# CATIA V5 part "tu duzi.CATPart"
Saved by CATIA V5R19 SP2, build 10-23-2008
Part number: tu duzi
Bounding box of the stored display mesh (mm): x -139.503 to 1318.778, y -749.046 to 748.093, z -3.905 to 999.658
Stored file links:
  C:\BEHROOZ\catia learning\tarh haye mashin\hb\tu duzi.CATPart
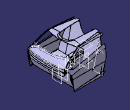
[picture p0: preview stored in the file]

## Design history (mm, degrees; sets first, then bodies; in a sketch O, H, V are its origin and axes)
Body1 (main body)
  DatumSurface1
  ThickSurface1: Surface DatumSurface1, TopOffset 6, BotOffset 0
  DatumSurface2
  ThickSurface2: Surface DatumSurface2, TopOffset 6, BotOffset 0
  DatumSurface3
  ThickSurface3: Surface DatumSurface3, TopOffset 6, BotOffset 0
  DatumSurface4
  ThickSurface4: Surface DatumSurface4, TopOffset 6, BotOffset 0
  DatumSurface5
  ThickSurface5: Surface DatumSurface5, TopOffset 6, BotOffset 0
  DatumSurface6
  ThickSurface6: Surface DatumSurface6, TopOffset 6, BotOffset 0
  DatumSurface7
  DatumSurface8
  ThickSurface7: Surface DatumSurface8, TopOffset 6, BotOffset 0
  DatumSurface9
  ThickSurface8: Surface DatumSurface9, TopOffset 6, BotOffset 0
  DatumSurface10
  ThickSurface9: Surface DatumSurface10, TopOffset 6, BotOffset 0
  DatumSurface11
  ThickSurface10: Surface DatumSurface11, TopOffset 6, BotOffset 0
  DatumSurface12
  ThickSurface11: Surface DatumSurface12, TopOffset 6, BotOffset 0
  DatumSurface13
  ThickSurface12: Surface DatumSurface13, TopOffset 6, BotOffset 0
  DatumSurface14
  ThickSurface13: Surface DatumSurface14, TopOffset 6, BotOffset 0
  DatumSurface15
  ThickSurface14: Surface DatumSurface15, TopOffset 6, BotOffset 0
  DatumSurface16
  ThickSurface15: Surface DatumSurface16, TopOffset 6, BotOffset 0
  DatumSurface17
  ThickSurface16: Surface DatumSurface17, TopOffset 6, BotOffset 0
  DatumSurface18
  ThickSurface17: Surface DatumSurface18, TopOffset 6, BotOffset 0
  DatumSurface19 to DatumSurface21
  ThickSurface18: Surface DatumSurface21, TopOffset 6, BotOffset -1
  DatumSurface22
  ThickSurface19: Surface DatumSurface22, TopOffset 6, BotOffset -1
  DatumSurface23
  ThickSurface20: Surface DatumSurface23, TopOffset 5, BotOffset -2
  DatumSurface24
  ThickSurface21: Surface DatumSurface24, TopOffset 5, BotOffset -2
  DatumSurface25
  ThickSurface22: Surface DatumSurface25, TopOffset 6, BotOffset -1
  DatumSurface26
  ThickSurface23: Surface DatumSurface26, TopOffset 13, BotOffset -2
  DatumSurface27
  ThickSurface24: Surface DatumSurface27, TopOffset 13, BotOffset -2
  DatumSurface28
  ThickSurface25: Surface DatumSurface28, TopOffset 13, BotOffset -2
  DatumSurface29
  ThickSurface26: Surface DatumSurface29, TopOffset 13, BotOffset -2
  DatumSurface30
  Sketch1 on zx-plane, origin (0, 0, 0), H (-1, 0, 0), V (0, 0, 1)
    arc A1 centre (-3834.746, 1334.3844) radius 3989.4624 from (142.7973, 1026.2291) to (-75.0584, 0.0082) cw
    arc A2 centre (-2062.7364, 65.3843) radius 1022.0278 from (-1272.4788, 713.4843) to (-1135.4173, 495.0587) cw
    line L1 (-1030.2634, -71.027) -> (-175.6467, -71.027)
    arc A3 centre (-175.6467, 35.7087) radius 106.7357 from (-75.0584, 0.0082) to (-175.6467, -71.027) cw
    line L2 (142.7973, 1026.2291) -> (1246.4568, 1192.5653)
    line L3 (1246.4568, 1192.5653) -> (1928.7231, 515.2608)
    line L4 (1928.7231, 515.2608) -> (858.0134, -421.0131)
    line L5 (858.0134, -421.0131) -> (-1407.9072, -550.4977)
    line L6 (-1407.9072, -550.4977) -> (-2393.9563, 86.9653)
    line L7 (-2393.9563, 86.9653) -> (-2120.0717, 949.2289)
    line L8 (-2120.0717, 949.2289) -> (-1272.4788, 713.4843)
    arc A4 centre (4413.6099, 1233.0151) radius 5597.882 from (-1135.4173, 495.0587) to (-1030.2634, -71.027) ccw
  Pocket1: profile Sketch1, direction (0, -1, 0), length 2693, mirrored extent
  DatumCurve1
  Point1: type OnCurve, Support DatumCurve1, Ratio 0.5
  Curve1: Elements (vertex [face of ThickSurface22 | face of ThickSurface22 | face of Pocket1 from Sketch1.A2]; Point1; vertex [face of ThickSurface19 | face of ThickSurface19 | face of Pocket1 from Sketch1.A2])
  Point2: (-243, -5, 9), relative to vertex of Curve1
  Point3: type OnCurve, Support Curve1, Ratio 0.13
  Point4: (-367, 0, 64), relative to Point3
  Point5: type OnCurve, Support Curve1, Ratio 0.37
  Point6: (-344, 0, 51), relative to Point5
  Point7: (-309, 0, 41), relative to Point1
  Point8: type OnCurve, Support Curve1, Ratio 0.77
  Point9: (-274, 0, 30), relative to Point8
  Symmetry1: ToTransfor Point2, Reference zx-plane
  Curve2: Elements (Symmetry1; Point9; Point7; Point6; Point4; Point2)
  Curve3: Elements (vertex of Curve1; Point2)
  Curve4: Elements (vertex of Curve1; Symmetry1)
  Corner1: Element1 Curve4, Element2 Curve2, Radius 107, Direction (0, 0, 1)
  Fill1: Boundary (Curve1; Corner1; Curve3)
  ThickSurface27: Surface Fill1, TopOffset 13, BotOffset -2
  Fillet1: radius 5, on face of ThickSurface27
  Plane1: type Offset, RefPlane xy-plane, Offset 449
  Sketch2 on Plane1, origin (0, 0, 449), H (1, 0, 0), V (0, 1, 0)
    line L1 (1222.6008, 607.4376) -> (1236.6342, 604.8067)
    arc A1 centre (1277.6367, -160.9425) radius 446.4787 from (1228.4764, -604.7066) to (1153.9503, -589.9471) cw
    arc A2 centre (-667.988, -264.4361) radius 1745.864 from (1066.9231, -459.6915) to (985.4739, 296.0145) ccw
    arc A3 centre (1220.2137, 375.581) radius 247.8581 from (985.4739, 296.0145) to (1057.5641, 562.607) cw
    arc A4 centre (1187.589, -473.2718) radius 121.4277 from (1153.9503, -589.9471) to (1066.9231, -459.6915) cw
    arc A5 centre (-4227.7674, 36.878) radius 5493.8354 from (1236.6342, 604.8067) to (1228.4764, -604.7066) cw
    arc A6 centre (1186.4195, 414.44) radius 196.3598 from (1057.5641, 562.607) to (1222.6008, 607.4376) cw
  Pad1: profile Sketch2, direction (0, 0, 1), up to face of ThickSurface27, opposite side length 18
  DatumCurve2
  RectPattern1: of ThickSurface27, direction 1 instances 2, spacing 98, along edge of DatumCurve2 reversed
  Fillet2: radius 5, on face of RectPattern1
  Plane2: type Offset, RefPlane yz-plane, Offset 694
  DatumSurface31
  Fillet3: radius 100, on edge [start face of Pad1 | face of Pad1 from Sketch2.A2]
  Join1: Elements (face of Pad1 from Sketch2.A3; face of Pad1 from Sketch2.A2)
  Plane3: type Offset, RefPlane Plane2, Offset 188
  Sketch3 on Plane3, origin (882, 0, 0), H (0, 1, 0), V (0, 0, 1)
    arc A1 centre (508.6645, 605.7318) radius 48.7497 from (541.1131, 569.3502) to (463.6433, 587.0334) ccw
    arc A2 centre (392.1984, 622.2132) radius 47.1664 from (427.7856, 591.258) to (354.8225, 593.4432) ccw
    circle A3 centre (306.2773, 645.6449) radius 20.4601
    circle A4 centre (328.066, 612.2053) radius 14.5415
    circle A5 centre (289.3627, 608.9891) radius 14.5415
    circle A6 centre (250.6593, 605.7729) radius 14.5415
    circle A7 centre (211.5999, 602.0845) radius 14.5415
    circle A8 centre (228.3164, 636.5264) radius 20.4601
    circle A9 centre (453.651, 648.3524) radius 14.4124
    point P14 (441.0167, 641.4177)
    point P15 (441.0167, 641.4177)
    circle A10 centre (450.4173, 620.326) radius 5.5628
    circle A11 centre (446.9694, 603.4744) radius 5.5628
    unspec C1
    unspec C2
    coincidence: P14 P15
  Translate1: ToTransfor Join1, Direction (1, 0, 0), Length 10
  Pocket2: profile Sketch3, direction (-1, 0, 0), up to Join1, opposite side up to Translate1
  Sketch4 on Plane3, origin (882, 0, 0), H (0, 1, 0), V (0, 0, 1)
    line L1 (-422.2542, 649.9754) -> (-243.5843, 649.9754)
    line L2 (-233.5843, 639.9754) -> (-233.5843, 588.5597)
    line L3 (-243.5843, 578.5597) -> (-422.2542, 578.5597)
    line L4 (-432.2542, 588.5597) -> (-432.2542, 639.9754)
    arc A1 centre (-422.2542, 639.9754) radius 10 from (-422.2542, 649.9754) to (-432.2542, 639.9754) ccw
    arc A2 centre (-243.5843, 639.9754) radius 10 from (-243.5843, 649.9754) to (-233.5843, 639.9754) cw
    arc A3 centre (-243.5843, 588.5597) radius 10 from (-233.5843, 588.5597) to (-243.5843, 578.5597) cw
    arc A4 centre (-422.2542, 588.5597) radius 10 from (-422.2542, 578.5597) to (-432.2542, 588.5597) cw
    circle A5 centre (-190.5814, 610.2491) radius 22.9588
    circle A6 centre (-190.5814, 610.2491) radius 16.1757
    arc A7 centre (-165.5799, 609.519) radius 17.9448 from (-178.9489, 621.4891) to (-179.6246, 598.3494) ccw
    arc A8 centre (-169.5141, 610.7067) radius 24.3411 from (-188.2423, 626.2547) to (-187.5495, 594.3601) ccw
    arc A9 centre (-184.614, 610.2457) radius 19.0479 from (-196.0659, 625.4666) to (-196.0833, 595.0378) ccw
    circle A10 centre (-32.537, 612.8316) radius 22.9588
    circle A11 centre (-32.537, 612.8316) radius 16.1757
    arc A12 centre (-7.5355, 612.1016) radius 17.9448 from (-20.9045, 624.0717) to (-21.5802, 600.932) ccw
    arc A13 centre (-11.4696, 613.2893) radius 24.3411 from (-30.1979, 628.8373) to (-29.505, 596.9426) ccw
    arc A14 centre (-26.5695, 612.8282) radius 19.0479 from (-38.0215, 628.0492) to (-38.0388, 597.6204) ccw
    circle A15 centre (32.6459, 612.8316) radius 22.9588
    circle A16 centre (32.6459, 612.8316) radius 16.1757
    arc A17 centre (7.6445, 612.1016) radius 17.9448 from (21.0135, 624.0717) to (21.6892, 600.932) cw
    arc A18 centre (11.5786, 613.2893) radius 24.3411 from (30.3068, 628.8373) to (29.614, 596.9426) cw
    arc A19 centre (26.6785, 612.8282) radius 19.0479 from (38.1305, 628.0492) to (38.1478, 597.6204) cw
    circle A20 centre (121.7133, 614.7218) radius 22.9588
    circle A21 centre (121.7133, 614.7218) radius 16.1757
    arc A22 centre (96.7118, 613.9917) radius 17.9448 from (110.0809, 625.9618) to (110.7565, 602.8221) cw
    arc A23 centre (100.646, 615.1794) radius 24.3411 from (119.3742, 630.7275) to (118.6814, 598.8328) cw
    arc A24 centre (115.7459, 614.7184) radius 19.0479 from (127.1979, 629.9393) to (127.2152, 599.5105) cw
  Pocket3: profile Sketch4, direction (-1, 0, 0), up to Join1, opposite side up to Translate1, thin wall 1
  ThickSurface28: Surface face of Pad1 from Sketch2.A2, TopOffset 3, BotOffset 0
  ThickSurface29: Surface face of Pad1 from Sketch2.A2, TopOffset 3, BotOffset 0
  ThickSurface30: Surface face of Pad1 from Sketch2.A2, TopOffset 3, BotOffset 0
  ThickSurface31: Surface face of Pad1 from Sketch2.A2, TopOffset 3, BotOffset 0
  Fillet4: radius 3, on edge [face of ThickSurface31 | face of ThickSurface31]; edge [face of ThickSurface30 | face of ThickSurface30]; edge [face of ThickSurface29 | face of ThickSurface29]; edge [face of ThickSurface28 | face of ThickSurface28]
  ThickSurface32: Surface face of Pad1 from Sketch2.A2, TopOffset 3, BotOffset 0
  Fillet5: radius 3, on face of ThickSurface32
  Pocket4: profile Sketch27, direction (-1, 0, 0), up to Join1, opposite side up to Translate1, offset 2
Body2
  DatumSurface32
  DatumSurface33
  Sketch5 on zx-plane, origin (0, 0, 0), H (-1, 0, 0), V (0, 0, 1)
    arc A1 centre (-1365.5691, 2023.2833) radius 1494.6313 from (-1057.7335, 560.6966) to (-1038.1843, 564.948) ccw
    line L1 (-743.7696, 307.1377) -> (-8.4597, 307.1377)
    line L2 (-8.4597, 307.1377) -> (12.6041, 35.1694)
    line L3 (12.6041, 35.1694) -> (-972.2409, 20.8529)
    arc A2 centre (-192.6492, 564.2855) radius 950.3063 from (-972.2409, 20.8529) to (-1142.7669, 545.3517) cw
    line L4 (-1142.7669, 545.3517) -> (-1057.7335, 560.6966)
    arc A3 centre (-743.7696, 434.0399) radius 126.9022 from (-805.8167, 323.3406) to (-743.7696, 307.1377) ccw
    arc A4 centre (-523.0393, 827.8481) radius 578.3518 from (-1038.1843, 564.948) to (-805.8167, 323.3406) ccw
  Pad2: profile Sketch5, direction (0, 1, 0), length 97, mirrored extent
  Chamfer1: length 63, angle 15, on edge [face of Pad2 from Sketch5.A4 | end face of Pad2]; edge [start face of Pad2 | face of Pad2 from Sketch5.A4]
  Fillet6: radius 10, on edge [face of Pad2 from Sketch5.L1 | face of Chamfer1]; edge [face of Chamfer1 | end face of Pad2]; edge [face of Chamfer1 | face of Pad2 from Sketch5.L1]; edge [start face of Pad2 | face of Chamfer1]
  Sketch6 on end face of Pad2, origin (0, 97, 0), H (-1, 0, 0), V (0, 0, 1)
    projected line E1 (-972.2409, 20.8529) -> (12.6041, 35.1694) from edge [face of Pad2 from Sketch5.L3 | end face of Pad2]
    projected arc E2 centre (-192.6492, 564.2855) radius 950.3063 from (-1142.7669, 545.3517) to (-972.2409, 20.8529) ccw from edge [face of Pad2 from Sketch5.A2 | end face of Pad2]
  Pad3: profile Sketch6, direction (0, 1, 0), length 589, opposite side length 787, thin wall 5
  Sketch7 on end face of Pad3, origin (0, 686, 0), H (-1, 0, 0), V (0, 0, 1)
    arc A1 centre (-192.6496, 564.2854) radius 950.306 from (-1140.061, 490.1699) to (-972.2409, 20.8529) ccw
    arc A2 centre (-192.6495, 564.2854) radius 945.306 from (-1135.4097, 494.9549) to (-969.6534, 25.8911) ccw
    line L1 (-969.6534, 25.8911) -> (12.5314, 40.1688)
    line L2 (12.5314, 40.1688) -> (12.6041, 35.1694)
    line L3 (12.6041, 35.1694) -> (-972.2409, 20.8529)
    line L4 (-1140.061, 490.1699) -> (-1135.4097, 494.9549)
  Pad4: profile Sketch7, direction (0, 1, 0), length 33
  Plane4: stored without definition
  Mirror1: of Pad4, about zx-plane
  Sketch8 on Plane4, origin (0, 334, 0), H (-1, 0, 0), V (0, 0, 1)
    line L1 (-1037.4943, 536.1759) -> (-864.9229, 611.7315)
    line L2 (-864.9229, 611.7315) -> (-824.0238, 536.1759)
    arc A1 centre (-1084.6874, 728.0864) radius 323.6899 from (-824.0238, 536.1759) to (-1108.6157, 405.2822) cw
    line L3 (-1108.6157, 405.2822) -> (-1037.4943, 536.1759)
  Pad5: profile Sketch8, direction (0, 1, 0), length -30, opposite side length -119
  Fillet7: radius 39, on edge [end face of Pad5 | face of Pad5 from Sketch8.A1]; edge [face of Pad5 from Sketch8.A1 | start face of Pad5]
  Fillet8: radius 26, on edge [face of Pad5 from Sketch8.L1 | start face of Pad5]; edge [end face of Pad5 | face of Pad5 from Sketch8.L1]
  Fillet9: radius 26, on face of Pad5 from Sketch8.L2
  Pocket5: profile Sketch19, direction (0, 0, -1), length 62
  Pocket6: profile Sketch24, direction (-1, 0, 0), length 42, opposite side length 403, thin wall 1
  Sketch9 on Plane2, origin (694, 0, 0), H (0, 1, 0), V (0, 0, 1)
    line L1 (58.921, 392.5908) -> (-58.8327, 392.5908)
    line L2 (-63.8327, 387.5908) -> (-63.8327, 343.9802)
    line L3 (-58.8327, 338.9802) -> (58.921, 338.9802)
    line L4 (63.921, 343.9802) -> (63.921, 387.5908)
    line L5 (33.921, 332.2071) -> (17.7613, 332.2071)
    line L6 (17.7613, 332.2071) -> (17.7613, 326.1764)
    line L7 (17.7613, 326.1764) -> (33.921, 326.1764)
    line L8 (33.921, 326.1764) -> (33.921, 332.2071)
    line L9 (16.0193, 332.2071) -> (-0.1405, 332.2071)
    line L10 (-0.1405, 332.2071) -> (-0.1405, 326.1764)
    line L11 (-0.1405, 326.1764) -> (16.0193, 326.1764)
    line L12 (16.0193, 326.1764) -> (16.0193, 332.2071)
    line L13 (-1.8825, 332.2071) -> (-18.0422, 332.2071)
    line L14 (-18.0422, 332.2071) -> (-18.0422, 326.1764)
    line L15 (-18.0422, 326.1764) -> (-1.8825, 326.1764)
    line L16 (-1.8825, 326.1764) -> (-1.8825, 332.2071)
    line L17 (-19.7842, 332.2071) -> (-35.944, 332.2071)
    line L18 (-35.944, 332.2071) -> (-35.944, 326.1764)
    line L19 (-35.944, 326.1764) -> (-19.7842, 326.1764)
    line L20 (-19.7842, 326.1764) -> (-19.7842, 332.2071)
    arc A1 centre (58.921, 343.9802) radius 5 from (58.921, 338.9802) to (63.921, 343.9802) ccw
    arc A2 centre (-58.8327, 387.5908) radius 5 from (-58.8327, 392.5908) to (-63.8327, 387.5908) ccw
    arc A3 centre (58.921, 387.5908) radius 5 from (58.921, 392.5908) to (63.921, 387.5908) cw
    arc A4 centre (-58.8327, 343.9802) radius 5 from (-63.8327, 343.9802) to (-58.8327, 338.9802) ccw
  Pocket7: profile Sketch9, direction (-1, 0, 0), length 42, opposite side length 259, thin wall 1
  Sketch10 on end face of Pad10, origin (0, 72, 0), H (-1, 0, 0), V (0, 0, 1)
    projected arc E1 centre (-702.5644, 421.2254) radius 220.3066 from (-525.3201, 290.3841) to (-502.088, 329.8789) ccw from edge [face of Fillet21 | end face of Pad10]
    projected arc E2 centre (-472.9683, 316.6106) radius 32 from (-475.2151, 348.5317) to (-502.088, 329.8789) ccw from edge [face of Fillet21 | end face of Pad10]
    projected arc E3 centre (-119.135, -4710.4762) radius 5071.5238 from (-60.1018, 360.704) to (-475.2151, 348.5317) ccw from edge [face of Fillet21 | end face of Pad10]
  Sketch11 on face of Pad5 from Sketch8.L2, origin (412.8217, 0, -223.465), H (0, -1, 0), V (0.476, 0, 0.8794)
    line L1 (-301.2089, 888.6024) -> (-472.1108, 888.6024)
    line L2 (-472.1108, 888.6024) -> (-472.1108, 926.6243)
    line L3 (-472.1108, 926.6243) -> (-301.2089, 926.6243)
    line L4 (-301.2089, 926.6243) -> (-301.2089, 888.6024)
  Pocket8: profile Sketch11, direction (0.8794, 0, -0.476), length 32, opposite side length -44
  Sketch12 on face of Pad5 from Sketch8.L2, origin (412.8217, 0, -223.465), H (0, -1, 0), V (0.476, 0, 0.8794)
    line L1 (-429.5392, 900.6907) -> (-541.6347, 912.8104)
    line L2 (-541.6347, 912.8104) -> (-540.6042, 922.3412)
    line L3 (-540.6042, 922.3412) -> (-428.5087, 910.2216)
    line L4 (-428.5087, 910.2216) -> (-429.5392, 900.6907)
    line L5 (-335.0437, 904.0642) -> (-229.239, 910.2216)
    line L6 (-229.239, 910.2216) -> (-229.8032, 919.9166)
    line L7 (-229.8032, 919.9166) -> (-335.6079, 913.7592)
    line L8 (-335.6079, 913.7592) -> (-335.0437, 904.0642)
  Pad6: profile Sketch12, direction (-0.8794, 0, 0.476), length -32, opposite side length 42
  Sketch13 on end face of Pad6, origin (440.9633, 0, -238.6983), H (0, -1, 0), V (0.476, 0, 0.8794)
    line L1 (-517.7755, 921.4397) -> (-555.3917, 930.3889)
    line L2 (-555.3917, 930.3889) -> (-558.0523, 911.042)
    line L3 (-558.0523, 911.042) -> (-519.6631, 908.7501)
    line L4 (-519.6631, 908.7501) -> (-517.7755, 921.4397)
    axis line L5 (-380.4079, 896.7881) -> (-380.4079, 939.3172)
    line L6 (-241.0901, 920.7533) -> (-206.5129, 928.7124)
    line L7 (-206.5129, 928.7124) -> (-204.5656, 909.1401)
    line L8 (-204.5656, 909.1401) -> (-239.9875, 907.9052)
    line L9 (-239.9875, 907.9052) -> (-241.0901, 920.7533)
  Pad7: profile Sketch13, direction (-0.8794, 0, 0.476), length -14, opposite side length -4
  Fillet10: radius 4.7, on edge [face of Pad6 from Sketch12.L3 | end face of Pad6]; edge [face of Pad6 from Sketch12.L1 | end face of Pad6]; edge [start face of Pad6 | face of Pad6 from Sketch12.L3]; edge [start face of Pad6 | face of Pad6 from Sketch12.L1]; edge [face of Pad6 from Sketch12.L5 | end face of Pad6]; edge [face of Pad6 from Sketch12.L7 | end face of Pad6]; edge [start face of Pad6 | face of Pad6 from Sketch12.L7]; edge [start face of Pad6 | face of Pad6 from Sketch12.L5]
  Fillet11: radius 5.7, on edge [face of Pad7 from Sketch13.L6 | start face of Pad7]; edge [end face of Pad7 | face of Pad7 from Sketch13.L6]; edge [face of Pad7 from Sketch13.L8 | start face of Pad7]; edge [end face of Pad7 | face of Pad7 from Sketch13.L8]; edge [face of Pad7 from Sketch13.L1 | start face of Pad7]; edge [end face of Pad7 | face of Pad7 from Sketch13.L1]; edge [face of Pad7 from Sketch13.L3 | start face of Pad7]; edge [end face of Pad7 | face of Pad7 from Sketch13.L3]
  Fillet12: radius 1.7, on face of Pad7 from Sketch13.L2; face of Pad7 from Sketch13.L7; edge [face of Pad7 from Sketch13.L6 | face of Pad7 from Sketch13.L9]; edge [face of Pad7 from Sketch13.L4 | face of Pad7 from Sketch13.L1]
Body3
  Point10: type OnPlane, Support face of Pad5 from Sketch8.L2, H -379.62, V 902.1, Direction (0, -1, 0)
  Line1: type PtDir, RefPoint Point10, Direction face of Pad5 from Sketch8.L2, Start -65, End 20
  Plane5: stored without definition
  Plane6: type OffsetPt, RefPlane Plane5, RefPoint Point10
  Sketch14 on Plane6, origin (0, 379.62, 0), H (-1, 0, 0), V (0, 0, 1)
    line L1 (-853.538, 590.6995) -> (-839.8717, 612.8699)
    line L2 (-839.8717, 612.8699) -> (-836.287, 610.6602)
    line L3 (-836.287, 610.6602) -> (-842.4641, 621.3408)
    line L4 (-842.5175, 570.3474) -> (-853.538, 590.6995)
    line L5 (-842.4641, 621.3408) -> (-831.283, 635.0107)
    arc A1 centre (-994.6494, 680.8433) radius 169.6738 from (-831.283, 635.0107) to (-825.716, 696.6769) ccw
    arc A2 centre (-429.2762, 749.9084) radius 386.03 from (-812.8779, 706.678) to (-785.8484, 602.0049) ccw
    line L6 (-785.8484, 602.0049) -> (-842.5175, 570.3474)
    arc A3 centre (-816.1033, 697.5778) radius 9.6549 from (-825.716, 696.6769) to (-812.8779, 706.678) cw
  Shaft1: profile Sketch14, axis Line1, angle 360
  Sketch15 on face of Pad5 from Sketch8.L2, origin (412.8217, 0, -223.465), H (0, -1, 0), V (0.476, 0, 0.8794)
    axis line L1 (-379.62, 902.1) -> (-381.6605, 970.3641)
    arc A1 centre (-379.62, 902.1) radius 101.5748 from (-343.7482, 997.1297) to (-417.6216, 996.2983) ccw
    arc A2 centre (-379.62, 902.1) radius 41.2983 from (-366.2993, 941.1911) to (-396.1276, 939.9557) ccw
    point P3 (-319.4813, 869.735)
    line L2 (-412.7546, 943.9571) -> (-426.6615, 960.9016)
    line L3 (-348.2831, 946.9114) -> (-334.4245, 966.0194)
    arc A3 centre (-401.7949, 952.952) radius 14.1783 from (-396.1276, 939.9557) to (-412.7546, 943.9571) cw
    arc A4 centre (-361.1661, 956.2552) radius 15.9147 from (-366.2993, 941.1911) to (-348.2831, 946.9114) ccw
    arc A5 centre (-350.9637, 978.0149) radius 20.4313 from (-343.7482, 997.1297) to (-334.4245, 966.0194) cw
    arc A6 centre (-409.1424, 975.2801) radius 22.6641 from (-417.6216, 996.2983) to (-426.6615, 960.9016) ccw
    point P16 (-439.4387, 863.0041)
    arc A7 centre (-381.3404, 898.9032) radius 101.5748 from (-481.5745, 882.4542) to (-443.9178, 818.8938) ccw
    arc A8 centre (-381.3404, 898.9032) radius 41.2983 from (-421.8546, 890.8937) to (-405.8706, 865.6794) ccw
    line L4 (-401.0224, 849.2793) -> (-408.7434, 828.7633)
    line L5 (-435.8167, 903.6361) -> (-459.294, 906.084)
    arc A9 centre (-414.2921, 854.2732) radius 14.1783 from (-405.8706, 865.6794) to (-401.0224, 849.2793) cw
    arc A10 centre (-437.4672, 887.8072) radius 15.9147 from (-421.8546, 890.8937) to (-435.8167, 903.6361) ccw
    arc A11 centre (-461.4128, 885.7629) radius 20.4313 from (-481.5745, 882.4542) to (-459.294, 906.084) cw
    arc A12 centre (-429.9551, 836.746) radius 22.6641 from (-443.9178, 818.8938) to (-408.7434, 828.7633) ccw
    point P29 (-317.573, 866.6467)
    arc A13 centre (-377.7117, 899.0117) radius 101.5748 from (-313.3495, 820.4309) to (-277.1328, 884.8228) ccw
    arc A14 centre (-377.7117, 899.0117) radius 41.2983 from (-350.5182, 867.9301) to (-336.6739, 894.3799) ccw
    line L6 (-324.8952, 906.7785) -> (-303.2673, 910.35)
    line L7 (-354.5724, 849.4674) -> (-344.9537, 827.9115)
    arc A15 centre (-322.5851, 892.7897) radius 14.1783 from (-336.6739, 894.3799) to (-324.8952, 906.7785) cw
    arc A16 centre (-340.0389, 855.9525) radius 15.9147 from (-350.5182, 867.9301) to (-354.5724, 849.4674) ccw
    arc A17 centre (-326.2956, 836.2371) radius 20.4313 from (-313.3495, 820.4309) to (-344.9537, 827.9115) cw
    arc A18 centre (-299.5747, 887.9888) radius 22.6641 from (-277.1328, 884.8228) to (-303.2673, 910.35) ccw
  Pocket9: profile Sketch15, direction (0.8794, 0, -0.476), length -120
  Fillet13: radius 11, on edge [face of Shaft1 from Sketch14.A2 | face of Pocket9 from Sketch15.A2]; edge [face of Shaft1 from Sketch14.A2 | face of Pocket9 from Sketch15.A8]; edge [face of Pocket9 from Sketch15.A14 | face of Shaft1 from Sketch14.A2]
  Fillet14: radius 1, on edge [face of Shaft1 from Sketch14.A1 | face of Pocket9 from Sketch15.L4]; edge [face of Pocket9 from Sketch15.L3 | face of Shaft1 from Sketch14.A1]; edge [face of Pocket9 from Sketch15.A13 | face of Shaft1 from Sketch14.A3]
  Fillet15: radius 2, on edge [face of Shaft1 from Sketch14.A2 | face of Shaft1 from Sketch14.A3]
  Fillet16: radius 7, on edge [face of Shaft1 from Sketch14.L3 | face of Pocket9 from Sketch15.A2]; edge [face of Pocket9 from Sketch15.A8 | face of Shaft1 from Sketch14.L3]; edge [face of Shaft1 from Sketch14.L3 | face of Pocket9 from Sketch15.A14]
  Sketch16 on zx-plane, origin (0, 0, 0), H (-1, 0, 0), V (0, 0, 1)
    arc A1 centre (-6403.7584, 2083.5089) radius 6583.0058 from (-148.0732, 33.5412) to (84.1276, 968.4757) ccw
  Pad8: profile Sketch16, direction (0, 1, 0), length -466, mirrored extent, thin wall 1
  Join2: Elements edge [start face of Pad8 | face of Pad8]
  Point11: type OnCurve, Support Join2, Ratio 0.5
  Point12: (0, 150, 90), relative to Point11
  Point13: type OnCurve, Support edge [face of Mirror1 | end face of Pad4], Ratio 0.16
  Curve5: Elements (Point13; Point12; vertex of Join2)
  Line2: type PtPt, FirstPoint vertex of Join2, SecondPoint Point13
  Fill2: Boundary (Line2; Join2; Curve5)
  Symmetry2: ToTransfor Fill2, Reference zx-plane
  ThickSurface33: Surface Fill2, TopOffset 1, BotOffset 0
  ThickSurface34: Surface Symmetry2, TopOffset 1, BotOffset 0
  DatumSurface34
  Sketch17 on yz-plane, origin (0, 0, 0), H (0, 1, 0), V (0, 0, 1)
    unspec C1
    unspec C2
    unspec C3
    unspec C4
    unspec C5
    unspec C6
    unspec C7
    unspec C8
    unspec C9
    unspec C10
    unspec C11
    unspec C12
    unspec C13
    unspec C14
    unspec C15
  Pocket10: profile Sketch17, direction (-1, 0, 0), length -279, opposite side length -137
  Sketch18 on Plane6, origin (0, 379.62, 0), H (-1, 0, 0), V (0, 0, 1)
    line L1 (-778.4005, 604.4606) -> (-798.3672, 594.2434)
    arc A1 centre (-829.8926, 578.1114) radius 57.8422 from (-778.4005, 604.4606) to (-795.1592, 624.364) ccw
    line L2 (-795.1592, 624.364) -> (-798.3672, 594.2434)
  Shaft2: profile Sketch18, axis Line1, angle 360
  Fillet17: radius 49, on edge [face of Shaft2 from Sketch18.A1 | face of Shaft1 from Sketch14.A2]
  Sketch19 on face of Pad2 from Sketch5.L1, origin (0, 0, 307.1377), H (1, 0, 0), V (0, 1, 0)
    line L1 (681.6123, 36.1442) -> (609.1396, 36.1442)
    line L2 (605.1396, 32.1442) -> (605.1396, 30.8304)
    line L3 (609.1396, 26.8304) -> (681.6123, 26.8304)
    line L4 (685.6123, 30.8304) -> (685.6123, 32.1442)
    line L5 (681.6123, -36.1442) -> (609.1396, -36.1442)
    line L6 (605.1396, -32.1442) -> (605.1396, -30.8304)
    line L7 (609.1396, -26.8304) -> (681.6123, -26.8304)
    line L8 (685.6123, -30.8304) -> (685.6123, -32.1442)
    arc A1 centre (681.6123, 32.1442) radius 4 from (681.6123, 36.1442) to (685.6123, 32.1442) cw
    arc A2 centre (609.1396, 32.1442) radius 4 from (605.1396, 32.1442) to (609.1396, 36.1442) cw
    arc A3 centre (609.1396, 30.8304) radius 4 from (605.1396, 30.8304) to (609.1396, 26.8304) ccw
    arc A4 centre (681.6123, 30.8304) radius 4 from (685.6123, 30.8304) to (681.6123, 26.8304) cw
    arc A5 centre (609.1396, -32.1442) radius 4 from (605.1396, -32.1442) to (609.1396, -36.1442) ccw
    arc A6 centre (681.6123, -32.1442) radius 4 from (681.6123, -36.1442) to (685.6123, -32.1442) ccw
    arc A7 centre (609.1396, -30.8304) radius 4 from (605.1396, -30.8304) to (609.1396, -26.8304) cw
    arc A8 centre (681.6123, -30.8304) radius 4 from (685.6123, -30.8304) to (681.6123, -26.8304) ccw
  Sketch20 on face of Pad5 from Sketch8.L2, origin (412.8217, 0, -223.465), H (0, -1, 0), V (0.476, 0, 0.8794)
    circle A1 centre (-379.5781, 901.1788) radius 31.6209
  Pocket11: profile Sketch20, direction (0.8794, 0, -0.476), length -39, opposite side length 109, thin wall 1
  Fillet18: radius 1.7, on face of Fillet17
  Fillet19: radius 1.7, on edge [face of Fillet17 | face of Pocket11]
Body4
  Sketch21 on face of Pad2 from Sketch5.L1, origin (0, 0, 307.1377), H (1, 0, 0), V (0, 1, 0)
    projected line E1 (685.6123, 30.8304) -> (685.6123, 32.1442) from edge [face of Pad2 from Sketch5.L1 | face of Pocket5 from Sketch19.L4]
    projected arc E2 centre (681.6123, 30.8304) radius 4 from (681.6123, 26.8304) to (685.6123, 30.8304) ccw from edge [face of Pad2 from Sketch5.L1 | face of Pocket5 from Sketch19.A4]
    projected line E3 (609.1396, 26.8304) -> (681.6123, 26.8304) from edge [face of Pad2 from Sketch5.L1 | face of Pocket5 from Sketch19.L3]
    projected arc E4 centre (609.1396, 30.8304) radius 4 from (605.1396, 30.8304) to (609.1396, 26.8304) ccw from edge [face of Pad2 from Sketch5.L1 | face of Pocket5 from Sketch19.A3]
    projected line E5 (605.1396, 32.1442) -> (605.1396, 30.8304) from edge [face of Pad2 from Sketch5.L1 | face of Pocket5 from Sketch19.L2]
    projected arc E6 centre (609.1396, 32.1442) radius 4 from (609.1396, 36.1442) to (605.1396, 32.1442) ccw from edge [face of Pad2 from Sketch5.L1 | face of Pocket5 from Sketch19.A2]
    projected line E7 (681.6123, 36.1442) -> (609.1396, 36.1442) from edge [face of Pad2 from Sketch5.L1 | face of Pocket5 from Sketch19.L1]
    projected arc E8 centre (681.6123, 32.1442) radius 4 from (685.6123, 32.1442) to (681.6123, 36.1442) ccw from edge [face of Pad2 from Sketch5.L1 | face of Pocket5 from Sketch19.A1]
    projected arc E9 centre (609.1396, -32.1442) radius 4 from (605.1396, -32.1442) to (609.1396, -36.1442) ccw from edge [face of Pad2 from Sketch5.L1 | face of Pocket5 from Sketch19.A5]
    projected line E10 (605.1396, -30.8304) -> (605.1396, -32.1442) from edge [face of Pad2 from Sketch5.L1 | face of Pocket5 from Sketch19.L6]
    projected arc E11 centre (609.1396, -30.8304) radius 4 from (609.1396, -26.8304) to (605.1396, -30.8304) ccw from edge [face of Pad2 from Sketch5.L1 | face of Pocket5 from Sketch19.A7]
    projected line E12 (681.6123, -26.8304) -> (609.1396, -26.8304) from edge [face of Pad2 from Sketch5.L1 | face of Pocket5 from Sketch19.L7]
    projected arc E13 centre (681.6123, -30.8304) radius 4 from (685.6123, -30.8304) to (681.6123, -26.8304) ccw from edge [face of Pad2 from Sketch5.L1 | face of Pocket5 from Sketch19.A8]
    projected line E14 (685.6123, -32.1442) -> (685.6123, -30.8304) from edge [face of Pad2 from Sketch5.L1 | face of Pocket5 from Sketch19.L8]
    projected arc E15 centre (681.6123, -32.1442) radius 4 from (681.6123, -36.1442) to (685.6123, -32.1442) ccw from edge [face of Pad2 from Sketch5.L1 | face of Pocket5 from Sketch19.A6]
    projected line E16 (609.1396, -36.1442) -> (681.6123, -36.1442) from edge [face of Pad2 from Sketch5.L1 | face of Pocket5 from Sketch19.L5]
    line L1 (690.439, 42.4459) -> (596.6334, 42.4459)
    line L2 (581.6334, 27.4459) -> (581.6334, -27.4459)
    line L3 (596.6334, -42.4459) -> (690.439, -42.4459)
    line L4 (710.439, -22.4459) -> (710.439, 22.4459)
    arc A1 centre (690.439, 22.4459) radius 20 from (690.439, 42.4459) to (710.439, 22.4459) cw
    arc A2 centre (690.439, -22.4459) radius 20 from (690.439, -42.4459) to (710.439, -22.4459) ccw
    arc A3 centre (596.6334, 27.4459) radius 15 from (581.6334, 27.4459) to (596.6334, 42.4459) cw
    arc A4 centre (596.6334, -27.4459) radius 15 from (581.6334, -27.4459) to (596.6334, -42.4459) ccw
  Pad9: profile Sketch21, direction (0, 0, 1), length 2
  Sketch22 on end face of Pad9, origin (0, 0, 309.1377), H (1, 0, 0), V (0, 1, 0)
    line L1 (610.2658, 19.3355) -> (610.2658, -20.6357)
    line L2 (632.9857, 19.3355) -> (632.9857, -20.6357)
    line L3 (655.7055, 19.3355) -> (655.7055, -20.6357)
    line L4 (678.4254, 19.3355) -> (678.4254, -20.6357)
    line L5 (620.3635, 12.1828) -> (620.3635, -10.9584)
    line L6 (643.5041, 12.1828) -> (643.5041, -10.9584)
    line L7 (666.6447, 12.1828) -> (666.6447, -10.9584)
    line L8 (689.7852, 12.1828) -> (689.7852, -10.9584)
  Pocket12: profile Sketch22, direction (0, 0, -1), length 2, thin wall 2
  Sketch23 on zx-plane, origin (0, 0, 0), H (-1, 0, 0), V (0, 0, 1)
    arc A1 centre (-702.5644, 421.2254) radius 197.3066 from (-554.2392, 291.1119) to (-512.3361, 368.8511) ccw
    arc A2 centre (-119.135, -4710.4762) radius 5094.5238 from (-512.3361, 368.8511) to (-52.4281, 383.6108) cw
    line L1 (-52.4281, 383.6108) -> (-87.3508, 279.3621)
    line L2 (-87.3508, 279.3621) -> (-554.2392, 291.1119)
  Pad10: profile Sketch23, direction (0, 1, 0), length 72, mirrored extent
  Fillet20: radius 55, on edge [face of Pad10 from Sketch23.A1 | face of Pad10 from Sketch23.A2]
  Fillet21: radius 23, on edge [face of Pad10 from Sketch23.A2 | end face of Pad10]; edge [start face of Pad10 | face of Pad10 from Sketch23.A2]
  Sketch24 on Plane2, origin (694, 0, 0), H (0, 1, 0), V (0, 0, 1)
    line L1 (58.921, 557.699) -> (-58.8327, 557.699)
    line L2 (-63.8327, 552.699) -> (-63.8327, 512.9541)
    line L3 (-58.8327, 507.9541) -> (58.921, 507.9541)
    line L4 (63.921, 512.9541) -> (63.921, 552.699)
    arc A1 centre (58.921, 552.699) radius 5 from (58.921, 557.699) to (63.921, 552.699) cw
    arc A2 centre (-58.8327, 552.699) radius 5 from (-58.8327, 557.699) to (-63.8327, 552.699) ccw
    arc A3 centre (-58.8327, 512.9541) radius 5 from (-63.8327, 512.9541) to (-58.8327, 507.9541) ccw
    arc A4 centre (58.921, 512.9541) radius 5 from (58.921, 507.9541) to (63.921, 512.9541) ccw
    line L5 (63.921, 499.8949) -> (-63.8327, 499.8949)
    line L6 (-63.8327, 499.8949) -> (-63.8327, 492.0671)
    line L7 (-63.8327, 492.0671) -> (63.921, 492.0671)
    line L8 (63.921, 492.0671) -> (63.921, 499.8949)
    line L9 (63.921, 488.8881) -> (-63.8327, 488.8881)
    line L10 (-63.8327, 488.8881) -> (-63.8327, 481.0603)
    line L11 (-63.8327, 481.0603) -> (63.921, 481.0603)
    line L12 (63.921, 481.0603) -> (63.921, 488.8881)
    line L13 (63.921, 477.8813) -> (-63.8327, 477.8813)
    line L14 (-63.8327, 477.8813) -> (-63.8327, 470.0536)
    line L15 (-63.8327, 470.0536) -> (63.921, 470.0536)
    line L16 (63.921, 470.0536) -> (63.921, 477.8813)
    line L17 (63.921, 466.8745) -> (-63.8327, 466.8745)
    line L18 (-63.8327, 466.8745) -> (-63.8327, 459.0468)
    line L19 (-63.8327, 459.0468) -> (63.921, 459.0468)
    line L20 (63.921, 459.0468) -> (63.921, 466.8745)
    line L21 (0.0442, 499.8949) -> (0.0442, 492.0671)
    line L22 (-38.0141, 499.8949) -> (-38.0141, 492.0671)
    line L23 (-46.0724, 499.8949) -> (-46.0724, 492.0671)
    line L24 (-54.1306, 499.8949) -> (-54.1306, 492.0671)
    line L25 (54.219, 499.8949) -> (54.219, 492.0671)
    line L26 (46.1607, 499.8949) -> (46.1607, 492.0671)
    line L27 (38.1025, 499.8949) -> (38.1025, 492.0671)
    line L28 (-54.1306, 488.8881) -> (-54.1306, 481.0603)
    line L29 (-46.0724, 488.8881) -> (-46.0724, 481.0603)
    line L30 (-38.0141, 488.8881) -> (-38.0141, 481.0603)
    line L31 (0.0442, 488.8881) -> (0.0442, 481.0603)
    line L32 (38.1025, 488.8881) -> (38.1025, 481.0603)
    line L33 (46.1607, 488.8881) -> (46.1607, 481.0603)
    line L34 (54.219, 488.8881) -> (54.219, 481.0603)
    line L35 (-54.1306, 477.8813) -> (-54.1306, 470.0536)
    line L36 (-46.0724, 477.8813) -> (-46.0724, 470.0536)
    line L37 (-38.0141, 477.8813) -> (-38.0141, 470.0536)
    line L38 (0.0442, 477.8813) -> (0.0442, 470.0536)
    line L39 (38.1025, 477.8813) -> (38.1025, 470.0536)
    line L40 (46.1607, 477.8813) -> (46.1607, 470.0536)
    line L41 (54.219, 477.8813) -> (54.219, 470.0536)
    line L42 (-54.1306, 466.8745) -> (-54.1306, 459.0468)
    line L43 (-46.0724, 466.8745) -> (-46.0724, 459.0468)
    line L44 (-38.0141, 466.8745) -> (-38.0141, 459.0468)
    line L45 (0.0442, 466.8745) -> (0.0442, 459.0468)
    line L46 (38.1025, 466.8745) -> (38.1025, 459.0468)
    line L47 (46.1607, 466.8745) -> (46.1607, 459.0468)
    line L48 (54.219, 466.8745) -> (54.219, 459.0468)
    line L49 (63.921, 453.5887) -> (-63.8327, 453.5887)
    line L50 (-63.8327, 453.5887) -> (-63.8327, 401.9804)
    line L51 (-63.8327, 401.9804) -> (63.921, 401.9804)
    line L52 (63.921, 401.9804) -> (63.921, 453.5887)
    line L53 (50.3376, 447.2968) -> (50.4789, 408.6712)
    line L54 (35.7363, 449.7294) -> (-58.7933, 449.7238)
    line L55 (-58.7933, 449.7238) -> (-58.7933, 413.3039)
    line L56 (-58.7933, 413.3039) -> (35.7363, 413.3095)
    line L57 (35.7363, 413.3095) -> (35.7363, 449.7294)
    line L58 (16.1607, 410.3685) -> (12.1579, 410.3685)
    line L59 (12.1579, 410.3685) -> (12.1579, 405.8047)
    line L60 (12.1579, 405.8047) -> (16.1607, 405.8047)
    line L61 (16.1607, 405.8047) -> (16.1607, 410.3685)
    line L62 (10.1698, 410.3685) -> (6.167, 410.3685)
    line L63 (6.167, 410.3685) -> (6.167, 405.8047)
    line L64 (6.167, 405.8047) -> (10.1698, 405.8047)
    line L65 (10.1698, 405.8047) -> (10.1698, 410.3685)
    line L66 (4.1789, 410.3685) -> (0.1761, 410.3685)
    line L67 (0.1761, 410.3685) -> (0.1761, 405.8047)
    line L68 (0.1761, 405.8047) -> (4.1789, 405.8047)
    line L69 (4.1789, 405.8047) -> (4.1789, 410.3685)
    line L70 (-1.812, 410.3685) -> (-5.8149, 410.3685)
    line L71 (-5.8149, 410.3685) -> (-5.8149, 405.8047)
    line L72 (-5.8149, 405.8047) -> (-1.812, 405.8047)
    line L73 (-1.812, 405.8047) -> (-1.812, 410.3685)
    line L74 (-7.8029, 410.3685) -> (-11.8058, 410.3685)
    line L75 (-11.8058, 410.3685) -> (-11.8058, 405.8047)
    line L76 (-11.8058, 405.8047) -> (-7.8029, 405.8047)
    line L77 (-7.8029, 405.8047) -> (-7.8029, 410.3685)
    line L78 (-13.7938, 410.3685) -> (-17.7967, 410.3685)
    line L79 (-17.7967, 410.3685) -> (-17.7967, 405.8047)
    line L80 (-17.7967, 405.8047) -> (-13.7938, 405.8047)
    line L81 (-13.7938, 405.8047) -> (-13.7938, 410.3685)
    line L82 (-19.7848, 410.3685) -> (-23.7876, 410.3685)
    line L83 (-23.7876, 410.3685) -> (-23.7876, 405.8047)
    line L84 (-23.7876, 405.8047) -> (-19.7848, 405.8047)
    line L85 (-19.7848, 405.8047) -> (-19.7848, 410.3685)
    line L86 (-25.7757, 410.3685) -> (-29.7785, 410.3685)
    line L87 (-29.7785, 410.3685) -> (-29.7785, 405.8047)
    line L88 (-29.7785, 405.8047) -> (-25.7757, 405.8047)
    line L89 (-25.7757, 405.8047) -> (-25.7757, 410.3685)
    circle A5 centre (-38.2072, 407.8576) radius 3.6696
    circle A6 centre (-46.7279, 407.8576) radius 3.6696
    circle A7 centre (-55.2487, 407.8576) radius 3.6696
    line L90 (42.2812, 447.2591) -> (40.1041, 447.2591)
    line L91 (40.1041, 447.2591) -> (40.1041, 436.4745)
    line L92 (40.1041, 436.4745) -> (42.2812, 436.4745)
    line L93 (42.2812, 436.4745) -> (42.2812, 447.2591)
    line L94 (42.2812, 433.6743) -> (40.1041, 433.6743)
    line L95 (40.1041, 433.6743) -> (40.1041, 422.8896)
    line L96 (40.1041, 422.8896) -> (42.2812, 422.8896)
    line L97 (42.2812, 422.8896) -> (42.2812, 433.6743)
    line L98 (42.2812, 420.0894) -> (40.1041, 420.0894)
    line L99 (40.1041, 420.0894) -> (40.1041, 409.3048)
    line L100 (40.1041, 409.3048) -> (42.2812, 409.3048)
    line L101 (42.2812, 409.3048) -> (42.2812, 420.0894)
  Pocket13: profile Sketch10, direction (0, -1, 0), length 126, opposite side length 14, thin wall 1
Body5
  Sketch25 on end face of Pocket5, origin (0, 0, 245.1377), H (1, 0, 0), V (0, 1, 0)
    circle A1 centre (644.6224, 31.5868) radius 3.8426
    circle A2 centre (644.6224, -31.5868) radius 3.8426
  Pad11: profile Sketch25, direction (0, 0, 1), length 120
  Sketch26 on zx-plane, origin (0, 0, 0), H (-1, 0, 0), V (0, 0, 1)
    circle A1 centre (-643.5054, 359.0763) radius 13.0562
  Pad12: profile Sketch26, direction (0, 1, 0), length 42, mirrored extent
  Sketch27 on Plane3, origin (882, 0, 0), H (0, 1, 0), V (0, 0, 1)
    circle A1 centre (522.6178, 646.7986) radius 3.0358
    circle A2 centre (503.9549, 648.8479) radius 3.0358
    circle A3 centre (486.1745, 642.8179) radius 3.0358
    circle A4 centre (472.6084, 629.8386) radius 3.0358
    circle A5 centre (465.7986, 612.342) radius 3.0358
    circle A6 centre (535.822, 639.5496) radius 3.0358
    circle A7 centre (545.7505, 628.2217) radius 3.0358
    circle A8 centre (551.206, 614.1812) radius 3.0358
    circle A9 centre (551.5303, 599.1216) radius 3.0358
    circle A10 centre (546.6843, 584.8593) radius 3.0358
    line L1 (508.6645, 599.1216) -> (513.4703, 603.4204)
    line L2 (513.4703, 603.4204) -> (521.0892, 639.5496)
    line L3 (521.0892, 639.5496) -> (503.9549, 608.1329)
    line L4 (503.9549, 608.1329) -> (504.5377, 600.3391)
    line L5 (504.5377, 600.3391) -> (504.5377, 595.4302)
    line L6 (504.5377, 595.4302) -> (508.6645, 599.1216)
    circle A11 centre (406.0226, 663.1396) radius 3.0358
    circle A12 centre (387.3597, 665.189) radius 3.0358
    circle A13 centre (369.5793, 659.159) radius 3.0358
    circle A14 centre (356.0132, 646.1797) radius 3.0358
    circle A15 centre (349.2034, 628.6831) radius 3.0358
    circle A16 centre (419.2268, 655.8907) radius 3.0358
    circle A17 centre (429.1553, 644.5628) radius 3.0358
    circle A18 centre (434.6108, 630.5223) radius 3.0358
    line L7 (404.494, 655.8907) -> (387.3597, 624.4739)
    circle A19 centre (430.0891, 601.2004) radius 3.0358
    circle A20 centre (434.9351, 615.4627) radius 3.0358
    line L8 (392.0692, 615.4627) -> (396.8751, 619.7615)
    line L9 (396.8751, 619.7615) -> (404.494, 655.8907)
    line L10 (387.9425, 611.7713) -> (392.0692, 615.4627)
    line L11 (387.9425, 616.6801) -> (387.9425, 611.7713)
    line L12 (387.3597, 624.4739) -> (387.9425, 616.6801)
    circle A21 centre (352.4787, 611.5) radius 3.2219
    circle A22 centre (463.4986, 643.448) radius 2.4087
    circle A23 centre (443.5551, 645.8712) radius 2.4087
    circle A24 centre (455.6203, 658.4226) radius 2.4087
    line L13 (455.6203, 646.7986) -> (455.6203, 655.4523)
    line L14 (455.6203, 655.4523) -> (452.5704, 647.5647)
    line L15 (452.5704, 647.5647) -> (452.4206, 640.455)
    line L16 (452.4206, 640.455) -> (455.6203, 646.7986)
